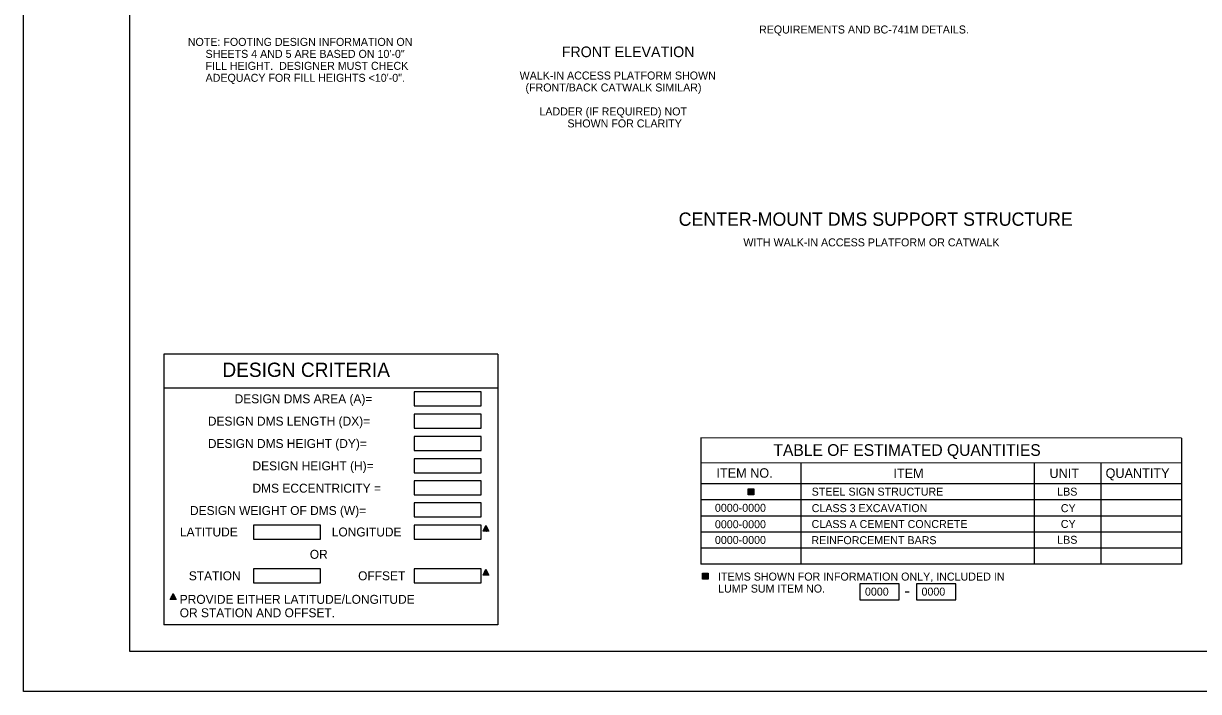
# Model space of a CAD drawing. Extents: x 3829340 to 3831660, y 499389 to 501171.
# Drawn here: x 3829340 to 3829781.8, y 499389.2 to 499640.3 of the extents above; entities that cross this region are included whole.
import ezdxf

# ---------------------------------------------------------------- set-up
doc = ezdxf.new("R2010")
doc.units = 0
for name, color, linetype in [('2', 7, 'Continuous'), ('DIM TXT', 7, 'Continuous'), ('PLT-BNDY', 7, 'Continuous')]:
    doc.layers.add(name, color=color, linetype=linetype)

msp = doc.modelspace()

# ---------------------------------------------------------------- linework, layer by layer
at = {"layer": '2'}
for p, q in [((3829379.96, 499404.19), (3829379.96, 499968.19)), ((3830165.96, 499404.19), (3829379.96, 499404.19))]:
    msp.add_line(p, q, dxfattribs=at)
at = {"layer": 'DIM TXT'}
for p, q in [((3829392.71, 499516.01), (3829392.71, 499414.26)), ((3829518.37, 499516.01), (3829392.71, 499516.01)), ((3829518.37, 499516.01), (3829518.37, 499414.26)), ((3829392.71, 499503.37), (3829518.37, 499503.37)), ((3829775.44, 499484.46), (3829594.68, 499484.47)), ((3829594.68, 499484.47), (3829594.68, 499437.01)), ((3829775.44, 499484.46), (3829775.44, 499437)), ((3829775.44, 499475.06), (3829594.68, 499475.07)), ((3829632.29, 499475.06), (3829632.29, 499437.01)), ((3829720.03, 499475.06), (3829720.03, 499437)), ((3829745.1, 499475.06), (3829745.1, 499437)), ((3829775.44, 499467.23), (3829594.68, 499467.23)), ((3829775.44, 499461.18), (3829594.68, 499461.19)), ((3829612.4, 499463.35), (3829614.35, 499465.3)), ((3829612.4, 499463.62), (3829614.09, 499465.3)), ((3829612.4, 499463.88), (3829613.82, 499465.3)), ((3829612.4, 499464.15), (3829613.56, 499465.3)), ((3829612.4, 499464.41), (3829613.29, 499465.3)), ((3829612.4, 499464.68), (3829613.03, 499465.3)), ((3829612.4, 499464.94), (3829612.76, 499465.3)), ((3829612.4, 499465.21), (3829612.5, 499465.3)), ((3829612.45, 499463.13), (3829614.57, 499465.26)), ((3829612.71, 499463.13), (3829614.57, 499464.99)), ((3829612.98, 499463.13), (3829614.57, 499464.73)), ((3829613.24, 499463.13), (3829614.57, 499464.46)), ((3829613.51, 499463.13), (3829614.57, 499464.2)), ((3829613.77, 499463.13), (3829614.57, 499463.93)), ((3829614.04, 499463.13), (3829614.57, 499463.67)), ((3829614.3, 499463.13), (3829614.57, 499463.4)), ((3829614.57, 499463.13), (3829614.57, 499463.14)), ((3829775.44, 499455.14), (3829594.68, 499455.14)), ((3829512.78, 499449.41), (3829514.21, 499450.83)), ((3829512.99, 499449.88), (3829514.12, 499451.01)), ((3829513.05, 499449.41), (3829514.3, 499450.66)), ((3829513.25, 499450.41), (3829514.03, 499451.19)), ((3829513.31, 499449.41), (3829514.39, 499450.48)), ((3829513.52, 499450.94), (3829513.94, 499451.36)), ((3829513.58, 499449.41), (3829514.47, 499450.3)), ((3829513.78, 499451.47), (3829513.86, 499451.54)), ((3829513.84, 499449.41), (3829514.56, 499450.13)), ((3829514.11, 499449.41), (3829514.65, 499449.95)), ((3829514.37, 499449.41), (3829514.74, 499449.77)), ((3829514.64, 499449.41), (3829514.83, 499449.6)), ((3829514.9, 499449.41), (3829514.92, 499449.42)), ((3829775.44, 499449.09), (3829594.68, 499449.1)), ((3829775.44, 499443.05), (3829594.68, 499443.05)), ((3829512.99, 499433.42), (3829514.12, 499434.55)), ((3829513.25, 499433.95), (3829514.03, 499434.72)), ((3829513.52, 499434.48), (3829513.94, 499434.9)), ((3829513.78, 499435.01), (3829513.86, 499435.08)), ((3829770.17, 499437), (3829594.68, 499437.01)), ((3829775.44, 499437), (3829594.68, 499437.01)), ((3829512.78, 499432.94), (3829514.21, 499434.37)), ((3829513.05, 499432.94), (3829514.3, 499434.19)), ((3829513.31, 499432.94), (3829514.39, 499434.02)), ((3829513.58, 499432.94), (3829514.47, 499433.84)), ((3829513.84, 499432.94), (3829514.56, 499433.66)), ((3829514.11, 499432.94), (3829514.65, 499433.49)), ((3829514.37, 499432.94), (3829514.74, 499433.31)), ((3829514.64, 499432.94), (3829514.83, 499433.13)), ((3829514.9, 499432.94), (3829514.92, 499432.96)), ((3829595.27, 499431.67), (3829597.22, 499433.62)), ((3829595.27, 499431.94), (3829596.96, 499433.62)), ((3829595.27, 499432.2), (3829596.69, 499433.62)), ((3829595.27, 499432.47), (3829596.42, 499433.62)), ((3829595.27, 499432.73), (3829596.16, 499433.62)), ((3829595.27, 499433), (3829595.89, 499433.62)), ((3829595.27, 499433.26), (3829595.63, 499433.62)), ((3829595.27, 499433.53), (3829595.36, 499433.62)), ((3829595.31, 499431.45), (3829597.44, 499433.58)), ((3829595.58, 499431.45), (3829597.44, 499433.31)), ((3829595.84, 499431.45), (3829597.44, 499433.05)), ((3829596.11, 499431.45), (3829597.44, 499432.78)), ((3829596.37, 499431.45), (3829597.44, 499432.52)), ((3829596.64, 499431.45), (3829597.44, 499432.25)), ((3829596.91, 499431.45), (3829597.44, 499431.99)), ((3829597.17, 499431.45), (3829597.44, 499431.72)), ((3829597.44, 499431.45), (3829597.44, 499431.46)), ((3829395.9, 499425.34), (3829396.33, 499425.76)), ((3829396.17, 499425.87), (3829396.24, 499425.94)), ((3829671.52, 499426.61), (3829672.99, 499426.61)), ((3829395.16, 499423.81), (3829396.59, 499425.23)), ((3829395.37, 499424.28), (3829396.5, 499425.41)), ((3829395.43, 499423.81), (3829396.68, 499425.06)), ((3829395.64, 499424.81), (3829396.42, 499425.59)), ((3829395.7, 499423.81), (3829396.77, 499424.88)), ((3829395.96, 499423.81), (3829396.86, 499424.7)), ((3829396.23, 499423.81), (3829396.95, 499424.53)), ((3829396.49, 499423.81), (3829397.04, 499424.35)), ((3829396.76, 499423.81), (3829397.12, 499424.17)), ((3829397.02, 499423.81), (3829397.21, 499424)), ((3829397.29, 499423.81), (3829397.3, 499423.82)), ((3829518.37, 499414.26), (3829392.71, 499414.26))]:
    msp.add_line(p, q, dxfattribs=at)
for points in [[(3829486.92, 499496.55), (3829512.11, 499496.55), (3829512.11, 499501.8), (3829486.92, 499501.8)], [(3829486.92, 499488.16), (3829512.11, 499488.16), (3829512.11, 499493.4), (3829486.92, 499493.4)], [(3829486.92, 499479.76), (3829512.11, 499479.76), (3829512.11, 499485.01), (3829486.92, 499485.01)], [(3829486.92, 499471.36), (3829512.11, 499471.36), (3829512.11, 499476.61), (3829486.92, 499476.61)], [(3829486.92, 499463.14), (3829512.11, 499463.14), (3829512.11, 499468.38), (3829486.92, 499468.38)], [(3829612.4, 499465.3), (3829614.57, 499465.3), (3829614.57, 499463.13), (3829612.4, 499463.13)], [(3829486.92, 499454.82), (3829512.11, 499454.82), (3829512.11, 499460.07), (3829486.92, 499460.07)], [(3829426.48, 499446.5), (3829451.67, 499446.5), (3829451.67, 499451.75), (3829426.48, 499451.75)], [(3829486.92, 499446.5), (3829512.11, 499446.5), (3829512.11, 499451.75), (3829486.92, 499451.75)], [(3829512.75, 499449.41), (3829513.84, 499451.58), (3829514.92, 499449.41)], [(3829426.48, 499430.04), (3829451.67, 499430.04), (3829451.67, 499435.29), (3829426.48, 499435.29)], [(3829486.92, 499430.04), (3829512.11, 499430.04), (3829512.11, 499435.29), (3829486.92, 499435.29)], [(3829512.75, 499432.94), (3829513.84, 499435.11), (3829514.92, 499432.94)], [(3829595.27, 499433.62), (3829597.44, 499433.62), (3829597.44, 499431.45), (3829595.27, 499431.45)], [(3829395.14, 499423.81), (3829396.22, 499425.98), (3829397.31, 499423.81)], [(3829654.45, 499423.65), (3829669.3, 499423.65), (3829669.3, 499429.64), (3829654.45, 499429.64)], [(3829675.7, 499423.65), (3829690.56, 499423.65), (3829690.56, 499429.64), (3829675.7, 499429.64)]]:
    msp.add_lwpolyline(points, close=True, dxfattribs=at)
at = {"layer": 'PLT-BNDY'}
msp.add_lwpolyline([(3829339.96, 499983.19), (3830180.96, 499983.19), (3830180.96, 499389.19), (3829339.96, 499389.19)], close=True, dxfattribs=at)

# ---------------------------------------------------------------- texts
at = {"layer": 'DIM TXT'}
for s, height, p in [('REQUIREMENTS AND BC-741M DETAILS.', 2.9999, (3829616.54, 499636.5)), ('NOTE: FOOTING DESIGN INFORMATION ON', 2.9999, (3829401.74, 499631.84)), ('      SHEETS 4 AND 5 ARE BASED ON 10\'-0"', 2.9999, (3829401.74, 499627.34)), ('FRONT ELEVATION', 3.9999, (3829542.35, 499627.61)), ('      FILL HEIGHT.  DESIGNER MUST CHECK', 2.9999, (3829401.74, 499622.84)), ('      ADEQUACY FOR FILL HEIGHTS <10\'-0".', 2.9999, (3829401.74, 499618.34)), ('WALK-IN ACCESS PLATFORM SHOWN ', 2.9999, (3829526.52, 499619.2)), ('(FRONT/BACK CATWALK SIMILAR)', 2.9999, (3829528.72, 499614.7)), ('LADDER (IF REQUIRED) NOT', 2.9999, (3829533.96, 499605.7)), ('SHOWN FOR CLARITY', 2.9999, (3829544.51, 499601.2)), ('CENTER-MOUNT DMS SUPPORT STRUCTURE', 4.9999, (3829586.32, 499564.22)), ('WITH WALK-IN ACCESS PLATFORM OR CATWALK', 2.9999, (3829610.66, 499556.49)), ('DESIGN CRITERIA', 5.3677, (3829414.75, 499507.42)), ('DESIGN DMS AREA (A)=', 3.3588, (3829419.36, 499497.51)), ('DESIGN DMS LENGTH (DX)=', 3.3588, (3829409.29, 499489.11)), ('DESIGN DMS HEIGHT (DY)=', 3.3588, (3829409.29, 499480.71)), ('TABLE OF ESTIMATED QUANTITIES', 4.3922, (3829621.96, 499477.74)), ('DESIGN HEIGHT (H)=', 3.3588, (3829426.08, 499472.31)), ('ITEM NO.', 3.557, (3829600.53, 499469.53)), ('ITEM', 3.557, (3829667.07, 499469.41)), ('UNIT', 3.557, (3829725.77, 499469.43)), ('QUANTITY', 3.557, (3829746.86, 499469.47)), ('DMS ECCENTRICITY =', 3.3588, (3829426.08, 499463.92)), ('STEEL SIGN STRUCTURE', 2.9999, (3829636.34, 499462.8)), ('LBS', 3, (3829728.67, 499462.79)), ('DESIGN WEIGHT OF DMS (W)=', 3.3588, (3829402.57, 499455.52)), ('0000-0000', 3, (3829599.96, 499456.72)), ('CLASS 3 EXCAVATION', 2.9999, (3829636.36, 499456.6)), ('CY', 3, (3829730.03, 499456.59)), ('0000-0000', 3, (3829599.96, 499450.55)), ('CLASS A CEMENT CONCRETE', 2.9999, (3829636.31, 499450.63)), ('CY', 3, (3829730.03, 499450.66)), ('LATITUDE', 3.359, (3829398.8, 499447.46)), ('LONGITUDE', 3.359, (3829455.89, 499447.46)), ('0000-0000', 3, (3829599.96, 499444.64)), ('REINFORCEMENT BARS', 2.9999, (3829636.24, 499444.57)), ('LBS', 3, (3829728.67, 499444.7)), ('OR', 3.359, (3829447.63, 499439.06)), ('STATION', 3.359, (3829402.13, 499430.99)), ('OFFSET', 3.359, (3829465.8, 499430.99)), ('ITEMS SHOWN FOR INFORMATION ONLY, INCLUDED IN', 3.0083, (3829601.14, 499430.87)), ('PROVIDE EITHER LATITUDE/LONGITUDE', 3.3588, (3829398.71, 499422.14)), ('LUMP SUM ITEM NO. ', 3.0083, (3829601.14, 499426.36)), ('0000', 3, (3829656.38, 499425.22)), ('0000', 3, (3829677.64, 499425.22)), ('OR STATION AND OFFSET.', 3.3588, (3829398.71, 499417.1))]:
    msp.add_text(s, height=height, dxfattribs=at).set_placement(p)

doc.saveas('drawing.dxf')
